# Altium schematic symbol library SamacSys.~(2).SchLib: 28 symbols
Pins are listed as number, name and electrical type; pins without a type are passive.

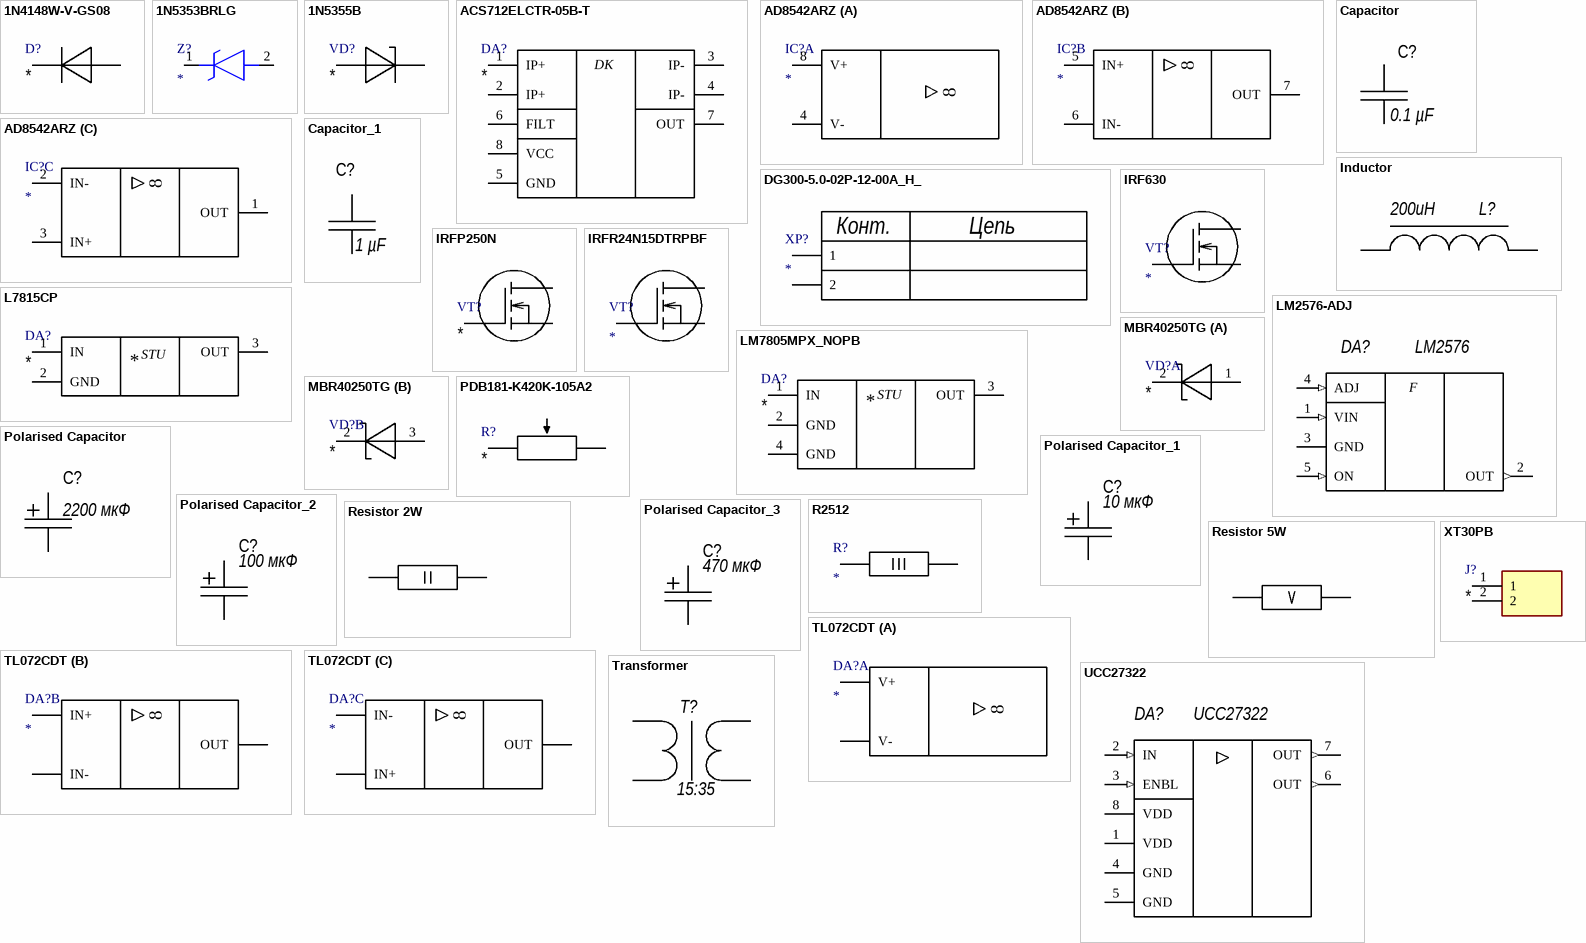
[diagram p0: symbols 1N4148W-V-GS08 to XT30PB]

## 1N4148W-V-GS08
designator D?
Diode; Manufacturer_Name: Vishay; Manufacturer_Part_Number: 1N4148W-V-GS08
footprint 1N4148WVGS08
pins: 1 K, 2 A

## 1N5353BRLG
designator Z?
Zener Diode; Manufacturer_Name: onsemi; Manufacturer_Part_Number: 1N5353BRLG
footprint DIOAD2260W109L864D349
pins: 1 K, 2 A

## 1N5355B
designator VD?
Zener Diode; Manufacturer_Name: Galaxy; Manufacturer_Part_Number: 1N5355B
footprint DIOAD2260W109L864D349
pins: 1 K, 2 A

## ACS712ELCTR-05B-T
designator DA?
ampermeter ic; Manufacturer_Name: Sharp Microelectronics; Manufacturer_Part_Number: ACS712ELCTR-05B-T
footprint SOIC127P600X175-8N
pins: 1 IP+ "1", 2 IP+ "2", 3 IP- "1", 4 IP- "2", 5 GND, 6 FILT, 7 OUT, 8 VCC

## AD8542ARZ
designator IC?
Integrated Circuit; Manufacturer_Name: Analog Devices; Manufacturer_Part_Number: AD8542ARZ
footprint SOIC127P600X175-8N
part A pins: 4 V-, 8 V+
part B pins: 5 IN+, 6 IN-, 7 OUT
part C pins: 1 OUT, 2 IN-, 3 IN+

## Capacitor
designator C?, comment value 0.1 µF  (hidden comment: 0.1 мкФ)
CAP CER 0.1UF 100V 1210; Part Number: 1210E104K101KHT; manufacturer: Knowles Novacap; Tolerance: ±10%
footprint CAP 1210_3225 - 1.2MM (Chip Capacitor, 2-Leads, Body 3.20x2.50mm, IPC Medium Density)
pins: 1, 2

## Capacitor_1
designator C?, comment Capacitance: 1 µF  (hidden comment: 1 мкФ)
CAP FILM 1UF 20% 35VDC 1210; Part Number: 35MU105MB13225; Manufacturer: Rubycon; Dielectric Material: Acrylic, Metallized; Value: 1 µF; Voltage Rating - DC: 35V
footprint CAP FILM 1210 (G2, Film Capacitor PPS, 2-Leads, Body 3.20x2.50mm, IPC Medium Density)
pins: 1, 2

## DG300-5.0-02P-12-00A_H_
designator XP?
Клеммник винтовой, 2-контактный, 5мм, прямой; Manufacturer_Name: Degson; Manufacturer_Part_Number: DG300-5.0-02P-12-00A(H)
footprint DG3005002P1200AH
pins: 1, 2

## Inductor
designator L?, comment 200uH
footprint IND_HCTI-220-5.8
pins: 1, 2

## IRF630
designator VT?
MOSFET (N-Channel)
footprint TO-220_STM
pins: 1 G, 2 D, 3 S

## IRFP250N
designator VT?
MOSFET (N-Channel); Manufacturer_Name: Infineon; Manufacturer_Part_Number: IRFP250N
footprint TO545P530X1560X2460-3P
pins: 1 G, 2 D, 3 S

## IRFR24N15DTRPBF
designator VT?
MOSFET (N-Channel)
footprint DPAK229P991X239-3N (D-PAK, 3-Pads, Body 6,21x6,73mm (max), IPC Medium Density for IRFR24N15DTRPBF)
pins: 1 G, 3 S, 4 D

## L7815CP
designator DA?
15 V Linear stab; Manufacturer_Name: STMicroelectronics; Manufacturer_Part_Number: L7815CP
footprint TO255P460X1020X2030-3P
pins: 1 IN (power), 2 GND (power), 3 OUT (power)

## LM2576-ADJ
designator DA?, comment LM2576
Buck-boost converter
footprint LM2576
pins: 1 VIN (in) "Информационный вход Х6", 2 OUT (out) "Информационный вход Х6", 3 GND (power) "Информационный вход Х6", 4 ADJ (in) "Информационный вход Х6", 5 ON (in) "Информационный вход Х6"

## LM7805MPX_NOPB
designator DA?
5 V Linear stab; Manufacturer_Name: Texas Instruments; Manufacturer_Part_Number: LM7805MPX/NOPB
footprint SOT230P700X180-4N
pins: 1 IN, 2 GND "1", 3 OUT, 4 GND "2"

## MBR40250TG
designator VD?
Shootky Diode; Manufacturer_Name: onsemi; Manufacturer_Part_Number: MBR40250TG
footprint TO254P483X1010X2035-3P
part A pins: 1 A_1, 2 K
part B pins: 2 K, 3 A_2

## PDB181-K420K-105A2
designator R?
Variable Resistor; Manufacturer_Name: Bourns; Manufacturer_Part_Number: PDB181-K420K-105A2
footprint PDB181K220K104B
pins: 1 CCW, 2 WIPER, 3 CW

## Polarised Capacitor
designator C?, comment 2200 мкФ
CAP ALUM 2200UF 20% 50V RADIAL; Part Number: 50RX302200M18X40; manufacturer: Rubycon; Capacitance: 2200µF; Impedance: 29 mOhms; Lifetime @ Temp.: 4000 Hrs @ 130°C; Polarization: Polar; Ripple Current @ High Frequency: 2.8A @ 100kHz; Ripple Current @ Low Frequency: 2.24A @ 120Hz; value: 2200µF
footprint CAP TH ALUM ELEC D18.00mm S7.50mm H42.00mm (18mm Diameter 7.5mm Lead Spacing Aluminum Electrolytic Capacitors Radial, Can)
pins: 1, 2

## Polarised Capacitor_1
designator C?, comment 10 мкФ
CAP ALUM 10UF 20% 16V RADIAL; Part Number: UPW1C100MDD; manufacturer: Nichicon; Capacitance: 10µF; Impedance: 600 mOhms; Lifetime @ Temp.: 2000 Hrs @ 105°C; Polarization: Polar; Ripple Current @ High Frequency: 180mA @ 100kHz; Ripple Current @ Low Frequency: 54mA @ 120Hz; value: 10µF
footprint CAP TH ALUM ELEC D5.00mm S2.00mm H11.00mm (5mm Diameter 2mm Lead Spacing Aluminum Electrolytic Capacitors Radial, Can)
pins: 1, 2

## Polarised Capacitor_2
designator C?, comment 100 мкФ
CAP ALUM 100UF 20% 25V RADIAL; Part Number: UKL1E101KPDANATD; manufacturer: Nichicon; Capacitance: 100µF; Lifetime @ Temp.: 1000 Hrs @ 105°C; Polarization: Polar; Ripple Current @ High Frequency: 420mA @ 10kHz; Ripple Current @ Low Frequency: 280mA @ 120Hz; Tolerance: ±10%; value: 100µF
footprint CAP TH ALUM ELEC D8.00mm S3.50mm H12.50mm (8mm Diameter 3.5mm Lead Spacing Aluminum Electrolytic Capacitors Radial, Can)
pins: 1, 2

## Polarised Capacitor_3
designator C?, comment 470 мкФ
CAP ALUM 470UF 20% 25V RADIAL; Part Number: 25WA470MEFCT810X9; manufacturer: Rubycon; Capacitance: 470µF; Lifetime @ Temp.: 2000 Hrs @ 85°C; Polarization: Polar; Ripple Current @ Low Frequency: 460mA @ 120Hz; value: 470µF
footprint CAP TH ALUM ELEC D18.00mm S7.50mm H42.00mm (18mm Diameter 7.5mm Lead Spacing Aluminum Electrolytic Capacitors Radial, Can)
pins: 1, 2

## R2512
designator R?
Resistor 3W; Manufacturer_Name: Bourns; Manufacturer_Part_Number: CRA2512-FZ-R050ELF
footprint RESC6434X90N
pins: 1 "*", 2 "*"

## Resistor 2W
designator R?
2W
footprint FP-MCS3264-IPC_A
pins: 1 "*", 2 "*"

## Resistor 5W
designator R?
5W
footprint RESAD2860W80L2200D950
pins: 1 "*", 2 "*"

## TL072CDT
designator DA?
Операционный усилитель, двухканальный, 13 В, 4 МГц; Manufacturer_Name: STMicroelectronics; Manufacturer_Part_Number: TL072CDT
footprint SOIC127P600X175-8N
part A pins: 4 V-, 8 V+
part B pins: 5 IN+, 6 IN-, 7 OUT
part C pins: 1 OUT, 2 IN-, 3 IN+

## Transformer
designator T?, comment 15:35
footprint WE-GDT_EP5 (Gate-Drive-Transformer, size EP5)
pins: 1 "Информационный вход Х6", 3 "Информационный вход Х6", 4 "Информационный вход Х6", 6 "Информационный вход Х6"

## UCC27322
designator DA?
Single 9-A High-Speed Low-Side Mosfet Driver With Enable
footprint SOIC127P599X175-8N
pins: 1 VDD (power), 2 IN (in), 3 ENBL (in), 4 GND (power) "A", 5 GND (power) "P", 6 OUT (out), 7 OUT (out), 8 VDD (power)

## XT30PB
designator J?
Connector; Manufacturer_Name: Amass; Manufacturer_Part_Number: XT30PB
footprint XT30PB
pins: 1, 2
